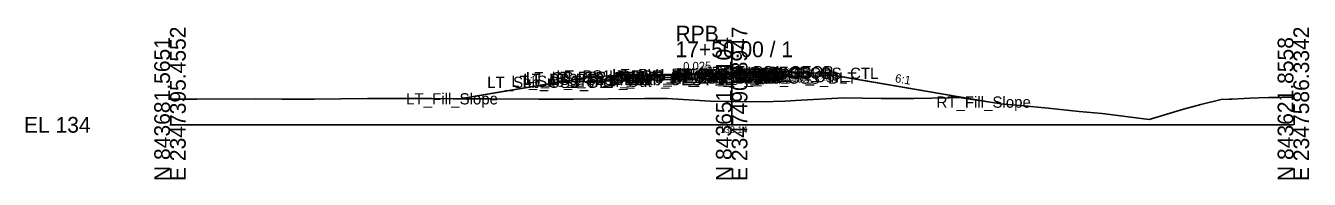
# Model space of a CAD drawing. Extents: x -76 to 2347760, y -10 to 844216.
# Drawn here: x -25.7 to 202.8, y 2490.3 to 2517.6 of the extents above; entities that cross this region are included whole.
import ezdxf

# ---------------------------------------------------------------- set-up
doc = ezdxf.new("R2010")
doc.units = 0
for name, color, linetype in [('Default', 7, 'Continuous'), ('Exist Cross Section Cell', 7, 'Continuous'), ('Exist XS Center Line Elevation Label', 7, 'Continuous'), ('Exist XS Ground Line', 7, 'Continuous'), ('Prop CMT Pvmt Course 1', 7, 'Continuous'), ('Prop CMT Pvmt Course 2', 7, 'Continuous'), ('Prop CMT Pvmt Course 3', 7, 'Continuous'), ('Prop CMT Pvmt Surface', 7, 'Continuous'), ('Prop CMT Pvmt Surface Shoulder', 7, 'Continuous'), ('Prop CMT Shld Paved Course 1', 7, 'Continuous'), ('Prop CMT Shld Paved Course 2', 7, 'Continuous'), ('Prop CMT Shld Paved Course 3', 7, 'Continuous'), ('Prop CMT Slope Grass', 7, 'Continuous'), ('Prop CMT Subgrade Earthwork', 7, 'Continuous'), ('Prop XS Earthwork Shape', 7, 'Continuous'), ('Prop XS SE Text', 7, 'Continuous'), ('Prop XS Side Slope Text', 7, 'Continuous'), ('Scratch_Level_0', 7, 'Continuous')]:
    doc.layers.add(name, color=color, linetype=linetype)

msp = doc.modelspace()

# ---------------------------------------------------------------- linework, layer by layer
at = {"layer": 'Exist Cross Section Cell'}
for p, q in [((100, 2500), (100, 2514.83)), ((0, 2500), (100, 2500)), ((100, 2500), (200, 2500))]:
    msp.add_line(p, q, dxfattribs=at)
at = {"layer": 'Exist XS Ground Line'}
msp.add_lwpolyline([(0, 2504.56), (4.79, 2504.55), (15.17, 2504.64), (19.9, 2504.57), (25.65, 2504.54), (35.15, 2504.7), (36.13, 2504.71), (38.29, 2504.71), (46.61, 2504.71), (50.4, 2504.64), (57.09, 2504.62), (65.64, 2504.59), (67.57, 2504.54), (71.79, 2504.58), (78.04, 2504.6), (84.53, 2504.7), (88.52, 2504.66), (96.14, 2504.23), (99, 2504.15), (100, 2504.14), (105.28, 2504.1), (109.48, 2504.18), (111.39, 2504.32), (119.96, 2504.82), (126.64, 2504.67), (130.43, 2504.67), (132.42, 2504.68), (138.78, 2504.81), (140.4, 2504.84), (140.91, 2504.81), (148.39, 2503.69), (151.39, 2503.41), (156.37, 2502.98), (161.87, 2502.35), (165.93, 2502), (174.32, 2500.97), (180.46, 2502.77), (182.85, 2503.44), (183.52, 2503.59), (187.12, 2504.49), (188.58, 2504.57), (189.12, 2504.59), (191.17, 2504.68), (192.24, 2504.73), (193.81, 2504.79), (195.62, 2504.84), (196.38, 2504.86), (197.38, 2504.89), (197.92, 2504.9), (199.02, 2504.93), (200, 2504.94)], dxfattribs=at)
at = {"layer": 'Prop CMT Pvmt Course 1'}
for p, q in [((100, 2509.25), (104, 2509.35)), ((104, 2509.35), (104, 2509.1)), ((100, 2509.25), (88, 2508.95)), ((88, 2508.7), (100, 2509)), ((88, 2508.95), (88, 2508.7)), ((100, 2509), (100, 2509.25)), ((100, 2509), (100, 2509.25)), ((100, 2509), (100, 2509.13)), ((100, 2509.13), (100, 2509.13)), ((100, 2509.13), (100, 2509)), ((100, 2509), (100, 2509.13)), ((100, 2509.13), (100, 2509.13)), ((100, 2509.13), (100, 2509)), ((104, 2509.1), (100, 2509)), ((100, 2509), (100, 2509)), ((100, 2509), (100, 2509))]:
    msp.add_line(p, q, dxfattribs=at)
at = {"layer": 'Prop CMT Pvmt Course 2'}
for p, q in [((100, 2509), (88, 2508.7)), ((88, 2508.7), (88, 2508.37)), ((88, 2508.37), (100, 2508.67)), ((100, 2509), (104, 2509.1)), ((100, 2508.67), (100, 2509)), ((100, 2508.67), (100, 2509)), ((104, 2508.77), (100, 2508.67)), ((104, 2509.1), (104, 2508.77))]:
    msp.add_line(p, q, dxfattribs=at)
at = {"layer": 'Prop CMT Pvmt Course 3'}
for p, q in [((100, 2508.67), (88, 2508.37)), ((88, 2508.37), (88, 2508.03)), ((88, 2508.03), (100, 2508.33)), ((100, 2508.67), (104, 2508.77)), ((100, 2508.33), (100, 2508.67)), ((100, 2508.33), (100, 2508.67)), ((104, 2508.43), (100, 2508.33)), ((104, 2508.77), (104, 2508.43))]:
    msp.add_line(p, q, dxfattribs=at)
at = {"layer": 'Prop CMT Pvmt Surface'}
for q in [(104, 2509.35), (88, 2508.95)]:
    msp.add_line((100, 2509.25), q, dxfattribs=at)
at = {"layer": 'Prop CMT Pvmt Surface Shoulder'}
for p, q in [((104, 2509.35), (108, 2509.45)), ((88, 2508.95), (78, 2508.7))]:
    msp.add_line(p, q, dxfattribs=at)
at = {"layer": 'Prop CMT Shld Paved Course 1'}
for p, q in [((104, 2509.35), (108, 2509.45)), ((104, 2509.1), (104, 2509.35)), ((108, 2509.45), (108.24, 2509.21)), ((78, 2508.7), (77.74, 2508.44)), ((77.74, 2508.44), (88, 2508.7)), ((88, 2508.95), (78, 2508.7)), ((88, 2508.7), (88, 2508.95)), ((108.24, 2509.21), (104, 2509.1))]:
    msp.add_line(p, q, dxfattribs=at)
at = {"layer": 'Prop CMT Shld Paved Course 2'}
for p, q in [((77.74, 2508.44), (77.4, 2508.1)), ((77.4, 2508.1), (88, 2508.37)), ((88, 2508.7), (77.74, 2508.44)), ((88, 2508.37), (88, 2508.7)), ((104, 2509.1), (108.24, 2509.21)), ((104, 2508.77), (104, 2509.1)), ((108.57, 2508.88), (104, 2508.77)), ((108.24, 2509.21), (108.57, 2508.88))]:
    msp.add_line(p, q, dxfattribs=at)
at = {"layer": 'Prop CMT Shld Paved Course 3'}
for p, q in [((76.9, 2508.09), (76.56, 2507.75)), ((76.56, 2507.75), (88, 2508.03)), ((77.4, 2508.1), (76.9, 2508.09)), ((88, 2508.37), (77.4, 2508.1)), ((88, 2508.03), (88, 2508.37)), ((104, 2508.77), (108.57, 2508.88)), ((104, 2508.43), (104, 2508.77)), ((109.39, 2508.57), (104, 2508.43)), ((108.57, 2508.88), (109.07, 2508.89)), ((109.07, 2508.89), (109.39, 2508.57))]:
    msp.add_line(p, q, dxfattribs=at)
at = {"layer": 'Prop CMT Slope Grass'}
for p, q in [((108, 2509.45), (116, 2509.17)), ((108, 2509.45), (116, 2509.17)), ((74, 2508.38), (51.52, 2504.63)), ((78, 2508.7), (74, 2508.38)), ((116, 2509.17), (146, 2504.04)), ((116, 2509.17), (146, 2504.04))]:
    msp.add_line(p, q, dxfattribs=at)
at = {"layer": 'Prop CMT Subgrade Earthwork'}
for p, q in [((76.56, 2507.75), (69.08, 2507.56)), ((88, 2508.03), (76.56, 2507.75)), ((100, 2508.33), (88, 2508.03)), ((100, 2508.33), (104, 2508.43)), ((104, 2508.43), (118.23, 2508.79))]:
    msp.add_line(p, q, dxfattribs=at)
at = {"layer": 'Prop XS Earthwork Shape'}
msp.add_lwpolyline([(51.52, 2504.63), (57.09, 2504.62), (65.64, 2504.59), (67.57, 2504.54), (71.79, 2504.58), (78.04, 2504.6), (84.53, 2504.7), (88.52, 2504.66), (96.14, 2504.23), (99, 2504.15), (100, 2504.14), (105.28, 2504.1), (109.48, 2504.18), (111.39, 2504.32), (119.96, 2504.82), (126.64, 2504.67), (130.43, 2504.67), (132.42, 2504.68), (138.78, 2504.81), (140.4, 2504.84), (140.91, 2504.81), (146, 2504.04), (118.23, 2508.79), (104, 2508.43), (100, 2508.33), (88, 2508.03), (76.56, 2507.75), (69.08, 2507.56)], close=True, dxfattribs=at)

# ---------------------------------------------------------------- texts
at = {"layer": 'Default'}
msp.add_text('-', height=0.0001, dxfattribs=at).set_placement((0, 2500))
at = {"layer": 'Exist Cross Section Cell'}
for s, p in [('E 2347395.4552', (2.8, 2490)), ('E 2347490.8947', (102.8, 2490)), ('E 2347586.3342', (202.8, 2490)), ('N 843681.5651', (0, 2490)), ('N 843651.7104', (100, 2490)), ('N 843621.8558', (200, 2490))]:
    msp.add_text(s, height=2.8, rotation=90, dxfattribs=at).set_placement(p)
for s, p in [('RPB', (90, 2514.83)), ('17+50.00 / 1', (90, 2512.03)), ('EL 134', (-26, 2498.6))]:
    msp.add_text(s, height=2.8, dxfattribs=at).set_placement(p)
at = {"layer": 'Exist XS Center Line Elevation Label'}
msp.add_text('138.14', height=1.2, dxfattribs=at).set_placement((97.89, 2498.54))
at = {"layer": 'Prop XS SE Text'}
msp.add_text('0.025', height=1.5, rotation=1.4321, dxfattribs=at).set_placement((91.38, 2509.64))
at = {"layer": 'Prop XS Side Slope Text'}
for rotation, p in [(9.4623, (63.1, 2507.15)), (350.5377, (129.01, 2507.59))]:
    msp.add_text('6:1', height=1.5, rotation=rotation, dxfattribs=at).set_placement(p)
at = {"layer": 'Scratch_Level_0'}
for s, p in [('LT_GS_OS_CTL', (63.37, 2507.38)), ('LT_PS2_OEOP', (67.98, 2507.44)), ('LT_PS1_OEOP', (68.8, 2507.7)), ('LT_PV2_OEOT', (78.17, 2507.7)), ('LT_PV3_OEOT', (78.17, 2507.37)), ('LT_PV1_OEOT', (78.74, 2507.95)), ('RT_Sub_OEEOP', (89.17, 2507.33)), ('LT_Sub_OEEOP', (89.21, 2507.33)), ('RT_PV2_OEEOP', (89.26, 2508)), ('RT_PV3_OEEOP', (89.26, 2507.67)), ('LT_PV2_OEEOP', (89.31, 2508)), ('LT_PV3_OEEOP', (89.31, 2507.67)), ('RT_PV1_OEEOP', (89.83, 2508.13)), ('LT_PV1_OEEOP', (89.87, 2508.13)), ('RT_PV2_IEEOP', (89.91, 2508)), ('LT_PV2_IEEOP', (89.95, 2508)), ('RT_PV1_IEEOP', (90.47, 2508.13)), ('LT_PV1_IEEOP', (90.52, 2508.13)), ('RT_Sub_Trench_Out', (93.55, 2507.57)), ('PV2_PGL', (93.91, 2508)), ('RT_Sub_OEOT', (94.03, 2507.43)), ('RT_PV2_OEOT', (94.13, 2508.1)), ('RT_PV3_OEOT', (94.13, 2507.77)), ('PV1_PGL', (94.47, 2508.25)), ('RT_PV1_OEOT', (94.69, 2508.35)), ('RT_PS3_Shelf_Out', (95.01, 2507.89)), ('RT_PS2_OEOP', (98.43, 2508.21)), ('RT_Sub_OSS_DLT', (98.75, 2507.31)), ('RT_PS1_OEOP', (98.76, 2508.45)), ('RT_PS3_OEOP', (98.76, 2507.88)), ('RT_GS_OS_CTL', (105.32, 2508.17)), ('LT_Sub_OSS_DLT', (56.48, 2506.56)), ('LT_Sub_Trench_Out', (60.76, 2506.75)), ('LT_PS3_Shelf_Out', (62.89, 2507.09)), ('LT_PS3_OEOP', (67.64, 2507.1)), ('LT_Sub_OEOT', (78.08, 2507.03)), ('LT_Fill_Slope', (42.04, 2503.63)), ('RT_Fill_Slope', (136.47, 2503.04))]:
    msp.add_text(s, height=2, dxfattribs=at).set_placement(p)

doc.saveas('drawing.dxf')
